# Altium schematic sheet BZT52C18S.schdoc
size 127 x 101 mm
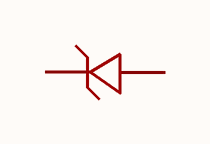
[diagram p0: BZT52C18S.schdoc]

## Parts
ZD?  bzt52c18s_c2106  [SOD-323_L1.8-W1.3-LS2.5-RD]  (value not drawn)

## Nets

Not connected (* = marked no-connect by the designer): ZD? 1(K) 2(A)

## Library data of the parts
ZD? = bzt52c18s_c2106: 二极管配置:1个独立式;稳压值(标称值):18V;稳压值(范围):16.8V~19.1V;耗散功率(Pd):200mW;; Manufacturer: CJ(江苏长电/长晶); AddInBom: yes; ModelId: db63db13d9e342eb939127d413d6200b; ModelTransform: 104.3305,51.181,0,0,0,0,0,-0.004,0; Diode Configuration: 1个独立式; Zener Voltage(Nom): 18V; Reverse Leakage Current (Ir): 100nA; Pd - Power Dissipation: 200mW; Impedance(Zzt): 45Ω; Impedance(Zzk): 225Ω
